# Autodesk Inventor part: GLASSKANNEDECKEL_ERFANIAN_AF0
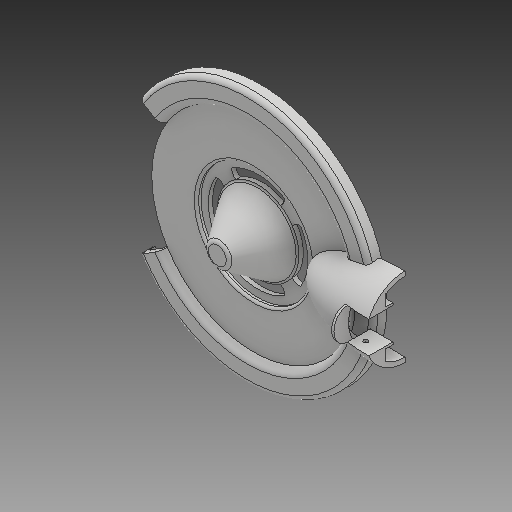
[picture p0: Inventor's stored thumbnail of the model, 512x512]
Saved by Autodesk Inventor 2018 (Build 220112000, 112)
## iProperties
Created: 2019-01
Part Number: GLASSKANNEDECKEL_ERFANIAN_AF0
Material: Polypropylene (PP)
Document SubType Name: Modeling
Designer: zand
Density: 0.902188 g/cm^3
Appearance: Vorgabe
Mass: 22.8074 g
Surface Area: 261.373 cm^2
Volume: 25.2801 cm^3
Author: zand
Revision Number: 20LAST_VERSION
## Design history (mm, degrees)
feature "Basis1"
node "Volumenkörper1"
